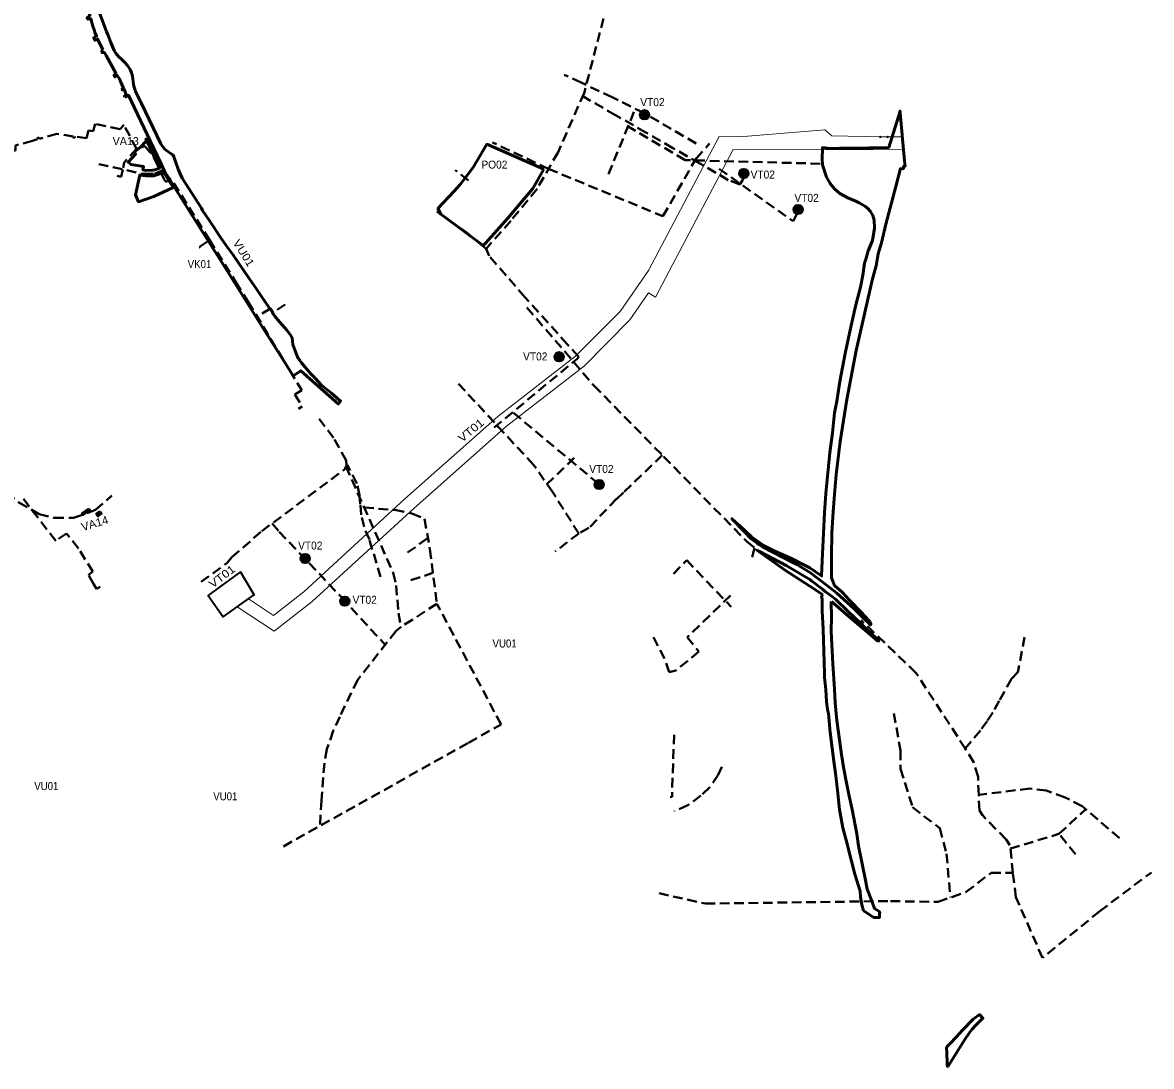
# Model space of a CAD drawing. Extents: x -650145 to -642675, y -1074338 to -1066803.
# Drawn here: x -647369 to -644548, y -1073665 to -1071056 of the extents above; entities that cross this region are included whole.
import ezdxf

# ---------------------------------------------------------------- set-up
doc = ezdxf.new("R2010")
doc.units = 0
doc.header["$LTSCALE"] = 8
doc.header["$PDMODE"] = 32
doc.header["$PDSIZE"] = 4
doc.linetypes.add('MEDIUM_DASHED', pattern=[4.5, 3, -1.5])
for name, color, linetype, lineweight in [('12', 7, 'MEDIUM_DASHED', 40), ('15', 7, 'Continuous', 13), ('45', 7, 'Continuous', 53), ('46', 7, 'Continuous', 53), ('53', 7, 'Continuous', 53), ('60', 7, 'Continuous', 53)]:
    doc.layers.add(name, color=color, linetype=linetype, lineweight=lineweight)
for name, color, linetype in [('17', 7, 'Continuous'), ('2', 7, 'Continuous'), ('3', 7, 'Continuous'), ('5', 7, 'Continuous'), ('8', 7, 'Continuous')]:
    doc.layers.add(name, color=color, linetype=linetype)

msp = doc.modelspace()

# ---------------------------------------------------------------- hatches: boundary and pattern name
at = {"layer": '15'}
for points in [[(-645802.757, -1071286.29, 1), (-645826.282, -1071286.29, 1)], [(-645554.856, -1071433.585, 1), (-645578.381, -1071433.585, 1)], [(-645418.959, -1071522.908, 1), (-645442.484, -1071522.908, 1)], [(-646016.453, -1071890.987, 1), (-646039.978, -1071890.987, 1)], [(-645916.109, -1072210.132, 1), (-645939.634, -1072210.132, 1)], [(-646651.182, -1072395.364, 1), (-646674.706, -1072395.364, 1)], [(-646551.973, -1072501.882, 1), (-646575.498, -1072501.882, 1)]]:
    msp.add_hatch(color=256, dxfattribs=at).paths.add_polyline_path(points)
at = {"layer": '60'}
for points in [[(-647203.48, -1072271.1), (-647219.86, -1072283.16), (-647217.95, -1072285.83), (-647201.52, -1072273.8)], [(-647175.95, -1072277.72), (-647183.77, -1072283.6), (-647179.89, -1072288.9), (-647172.06, -1072283.01)]]:
    msp.add_hatch(color=256, dxfattribs=at).paths.add_polyline_path(points)

# ---------------------------------------------------------------- linework, layer by layer
at = {"layer": '12'}
for p, q in [((-645904.71, -1071434.718), (-645838.309, -1071272.923)), ((-645713.277, -1071399.789), (-645855.82, -1071315.589)), ((-646054.42, -1071421.627), (-646194.458, -1071355.655)), ((-645375.745, -1071408.757), (-645713.277, -1071399.789)), ((-646254.398, -1071450.366), (-646287.777, -1071424.84)), ((-646142.308, -1072031.286), (-645934.368, -1072204.655)), ((-645990.194, -1072143.593), (-646067.454, -1072218.303)), ((-646406.679, -1072380.519), (-646355.921, -1072344.291)), ((-646398.36, -1072449.736), (-646343.369, -1072431.172)), ((-644737.523, -1073134.312), (-644778.948, -1073083.582)), ((-644677.063, -1073276.773), (-644547.878, -1073179.588))]:
    msp.add_line(p, q, dxfattribs=at)
for points in [[(-645889.511, -1070941.335), (-645965.547, -1071232.088), (-646030.617, -1071380.071), (-646083.181, -1071471.838), (-646148.926, -1071551.731), (-646210.712, -1071621.148), (-646257.454, -1071581.884), (-646334.001, -1071528.434)], [(-645685.92, -1071358.056), (-645816.424, -1071281.963), (-645895.068, -1071242.641), (-645972.753, -1071206.196), (-646015.628, -1071186.357)], [(-645568.545, -1071446.977), (-645568.85, -1071448.81), (-645576.682, -1071460.349), (-645605.23, -1071449.68), (-645676.24, -1071408.26), (-645743.83, -1071369.64), (-645811.23, -1071330.74), (-645886.93, -1071287.36), (-645969.116, -1071240.205)], [(-647125.34, -1071322.14), (-647187.77, -1071309.47), (-647192.05, -1071327.84), (-647204.02, -1071325.39), (-647208.89, -1071345.24), (-647238.16, -1071341.03), (-647238.54, -1071343.71), (-647242.66, -1071343.12), (-647242.27, -1071340.44), (-647283.52, -1071334.51), (-647326.47, -1071346.51), (-647327.32, -1071343.47), (-647332.03, -1071344.79), (-647331.18, -1071347.82), (-647344.33, -1071351.49)], [(-647084.37, -1071371.2), (-647115.91, -1071311.35), (-647125.34, -1071322.14)], [(-647344.33, -1071351.49), (-647386.85, -1071363.37), (-647386.8, -1071375.58), (-647438.34, -1071382.93)], [(-647084.37, -1071371.2), (-647115.19, -1071405.75), (-647117.79, -1071418.96)], [(-646901.7, -1071599.29), (-646997.62, -1071446.82), (-647011, -1071454.09), (-647015.17, -1071448), (-647045.84, -1071382.28), (-647050.73, -1071380.13), (-647063.41, -1071364.59), (-647084.37, -1071371.2)], [(-646054.42, -1071421.627), (-645768.62, -1071540.17), (-645685.873, -1071396.078), (-645651.868, -1071358.68)], [(-647178.442, -1071409.986), (-647065.935, -1071434.456), (-647038.805, -1071433.925), (-647016.651, -1071423.819)], [(-647118.63, -1071423.24), (-647122.21, -1071441.39), (-647132.07, -1071439.37)], [(-645627.85, -1071421.652), (-645443.026, -1071552.428), (-645433.722, -1071535.133)], [(-646925.38, -1071619.26), (-646926.8, -1071616.72), (-646901.7, -1071599.29)], [(-646901.7, -1071599.29), (-646836.01, -1071704.74), (-646804.94, -1071754.31)], [(-645979.173, -1071891.235), (-646007.318, -1071860.17), (-646113.522, -1071742.176), (-646203.196, -1071638.82), (-646210.712, -1071621.148)], [(-646804.94, -1071754.31), (-646701.24, -1071925.46), (-646671.37, -1071974.86)], [(-646712.71, -1071760.64), (-646743.06, -1071780.15), (-646749.35, -1071770.55), (-646782.673, -1071791.06)], [(-646108.34, -1071768.288), (-645991.774, -1071903.675), (-645940.8, -1071963.54), (-645766.873, -1072140.424), (-645559.153, -1072352.891), (-645539.728, -1072368.513), (-645547.013, -1072398.199)], [(-646190.163, -1072068.09), (-645983.794, -1071896.963), (-645979.173, -1071891.234)], [(-645978.908, -1072332.844), (-646044.53, -1072228.907), (-646091.859, -1072161.141), (-646284.4, -1071953.541)], [(-646671.37, -1071974.86), (-646688.66, -1071985.16), (-646669.77, -1072015.67), (-646679.35, -1072021.71)], [(-647565.274, -1072012.581), (-647407.42, -1072230.889), (-647378.312, -1072255.368), (-647327.486, -1072284.458), (-647289.597, -1072293.583), (-647241.628, -1072293.997), (-647186.201, -1072273.818), (-647145.51, -1072238.04)], [(-646922.495, -1072453.643), (-646857.191, -1072406.111), (-646845.696, -1072392.061), (-646770.684, -1072326.695), (-646564.651, -1072173.134), (-646559.323, -1072162.51), (-646560.242, -1072150.62), (-646591.477, -1072093.57), (-646627.948, -1072046.396)], [(-646515.621, -1072316.407), (-646522.296, -1072286.272), (-646525.05, -1072259.936), (-646526.73, -1072237.276), (-646533.563, -1072207.871), (-646557.282, -1072161.242)], [(-645770.117, -1072137.125), (-645867.081, -1072230.375), (-645887.539, -1072249.441)], [(-646560.829, -1072165.418), (-646442.617, -1072430.974), (-646435.336, -1072462.744), (-646429.379, -1072531.58), (-646422.811, -1072565.755), (-646435.637, -1072576.085), (-646531.76, -1072698.93), (-646576.398, -1072790.696), (-646592.362, -1072826.343), (-646608.607, -1072871.571), (-646614.559, -1072906.613), (-646622.02, -1072999.792), (-646625.456, -1073063.469)], [(-647191.37, -1072458.86), (-647204.41, -1072436.35), (-647193.17, -1072428.14), (-647228.9, -1072369.98), (-647259.29, -1072332.91), (-647286.03, -1072350.98), (-647368.027, -1072244.683)], [(-645884.618, -1072246.363), (-645953.602, -1072319.058), (-645978.908, -1072332.844), (-646038.138, -1072377.943)], [(-646515.068, -1072268.004), (-646438.375, -1072274.017), (-646395.81, -1072282.852), (-646364.347, -1072296.336), (-646351.055, -1072371.983), (-646333.32, -1072508.549)], [(-646744.92, -1072307.492), (-646727.261, -1072328.683), (-646572.036, -1072491.987), (-646462.937, -1072610.974)], [(-646474.01, -1072441.461), (-646502.208, -1072348.07), (-646515.621, -1072316.407)], [(-645742.473, -1072433.786), (-645709.258, -1072399.404), (-645598.422, -1072516.199)], [(-647175.32, -1072466), (-647184.36, -1072470.98), (-647191.37, -1072458.86)], [(-645599.642, -1072487.459), (-645707.673, -1072591.746), (-645678.856, -1072628.004), (-645736.077, -1072674.835), (-645752.766, -1072679.471), (-645764.412, -1072645.375), (-645793.32, -1072590.47)], [(-646716.85, -1073114.625), (-646254.197, -1072855.664), (-646173.155, -1072809.893), (-646333.32, -1072508.549), (-646422.811, -1072565.755)], [(-644677.063, -1073276.773), (-644820.09, -1073393.239), (-644886.431, -1073241.755), (-644894.218, -1073180.725), (-644901.367, -1073111.484), (-644910.953, -1073097.104), (-644970.414, -1073037.091), (-644977.617, -1073024.956), (-644979.519, -1072985.65), (-644981.225, -1072940.656), (-644991.691, -1072905.052), (-645013.264, -1072869.98), (-645136.284, -1072680.783), (-645273.573, -1072549.71)], [(-644865.163, -1072591.801), (-644881.47, -1072679.739), (-644897.776, -1072696.046), (-644928.014, -1072751.285)], [(-644928.014, -1072751.285), (-644944.228, -1072780.29), (-644958.247, -1072801.452), (-644975.175, -1072824.929), (-645013.264, -1072869.98)], [(-645191.679, -1072782.461), (-645175.001, -1072875.23), (-645175.001, -1072921.093), (-645144.773, -1073016.989), (-645077.02, -1073069.106), (-645059.861, -1073133.007), (-645050.18, -1073242.481)], [(-645740.627, -1072835.69), (-645745.906, -1072985.427), (-645745.265, -1072991.028), (-645750.784, -1072992.05)], [(-645621.405, -1072915.798), (-645630.523, -1072936.275), (-645652.44, -1072967.63), (-645673.716, -1072987.946), (-645706.351, -1073011.942), (-645739.675, -1073026.324)], [(-644627.418, -1073093.922), (-644720.94, -1073014.135), (-644763.53, -1072992.287), (-644810.544, -1072975.14), (-644851.751, -1072970.162), (-644979.519, -1072985.65)], [(-644900.454, -1073120.324), (-644778.948, -1073083.582), (-644712.07, -1073021.703)], [(-645777.988, -1073231.981), (-645662.45, -1073257.758), (-645199.545, -1073251.421), (-645080.605, -1073253.501), (-645010.848, -1073228.236), (-644948.284, -1073180.725), (-644894.218, -1073180.725)]]:
    msp.add_lwpolyline(points, dxfattribs=at)
at = {"layer": '15'}
msp.add_line((-645225.385, -1071341.796), (-645207.234, -1071341.824), dxfattribs=at)
at = {"layer": '15', "lineweight": 35}
msp.add_line((-646832.318, -1072516.145), (-646804.328, -1072496.262), dxfattribs=at)
at = {"layer": '15'}
for points in [[(-645987.337, -1071889.954), (-645875.751, -1071778.476), (-645805.025, -1071675.361), (-645627.872, -1071341.184), (-645577.351, -1071341.261), (-645364.122, -1071324.271), (-645346.46, -1071338.849), (-645225.385, -1071341.796)], [(-645207.234, -1071341.824), (-645170.274, -1071341.88), (-645167.04, -1071373.884), (-645592.784, -1071373.238), (-645786.781, -1071742.105), (-645804.579, -1071731.285)], [(-645804.579, -1071731.285), (-645850.985, -1071798.942), (-645964.716, -1071913.914)], [(-646665.903, -1072478.366), (-646413.327, -1072245.835), (-646181.43, -1072040.387), (-645987.337, -1071889.954)], [(-645964.716, -1071913.914), (-646159.64, -1072064.991), (-646390.555, -1072269.569), (-646645.209, -1072502.744)], [(-646645.209, -1072502.744), (-646739.733, -1072577.115), (-646832.318, -1072516.145), (-646804.328, -1072496.262)], [(-646804.328, -1072496.262), (-646741.387, -1072537.711), (-646665.903, -1072478.366)]]:
    msp.add_lwpolyline(points, dxfattribs=at)
at = {"layer": '15', "lineweight": 35}
msp.add_lwpolyline([(-646824.42, -1072428.58), (-646878.91, -1072468.54), (-646905.18, -1072487.8), (-646867.283, -1072540.984), (-646791.569, -1072487.198), (-646790.354, -1072486.136), (-646810.77, -1072451.09)], close=True, dxfattribs=at)
for centre in [(-645814.519, -1071286.29), (-645566.618, -1071433.585), (-645430.721, -1071522.908), (-646028.216, -1071890.987), (-645927.872, -1072210.132), (-646662.944, -1072395.364), (-646563.736, -1072501.882)]:
    msp.add_circle(centre, 11.762, dxfattribs=at)
at = {"layer": '15'}
for p in [(-645225.385, -1071341.796), (-645207.234, -1071341.824)]:
    msp.add_point(p, dxfattribs=at)
at = {"layer": '45'}
msp.add_line((-645267.525, -1073275.443), (-645271.518, -1073261.16), dxfattribs=at)
msp.add_lwpolyline([(-645222.48, -1071606.08), (-645211.27, -1071560.01), (-645186.67, -1071465.55), (-645175.06, -1071420.93), (-645167.58, -1071421.19), (-645167.37, -1071415.2), (-645163.56, -1071415.3), (-645164.76, -1071401.79), (-645175.4, -1071281.93), (-645175.67, -1071279.45), (-645176.14, -1071277.26), (-645204.341, -1071368.19), (-645243.3, -1071369.02), (-645254.27, -1071369.05), (-645327.08, -1071370.05), (-645348.55, -1071370.559), (-645370.24, -1071368.628), (-645370.24, -1071371.074), (-645370.393, -1071396.574), (-645370.24, -1071411.83), (-645359.64, -1071442), (-645351.06, -1071458.3), (-645340.16, -1071471.63), (-645326.29, -1071483.41), (-645306.77, -1071494.16), (-645286.62, -1071502.67), (-645278.52, -1071506.12), (-645262.36, -1071515.72), (-645255.51, -1071521.55), (-645249.88, -1071528.19), (-645244.4, -1071538.48), (-645240.82, -1071549.6), (-645240.26, -1071569.52), (-645244.81, -1071600.61), (-645248.786, -1071610.383), (-645255.662, -1071626.67), (-645261.094, -1071645.025), (-645264.841, -1071657.687), (-645269.077, -1071687.396), (-645274.868, -1071717.176), (-645286.175, -1071761.228), (-645300.076, -1071820.179), (-645313.153, -1071883.081), (-645326.343, -1071952.807), (-645334.118, -1072001.954), (-645339.455, -1072031.565), (-645344.819, -1072081.225), (-645351.358, -1072130.815), (-645361.317, -1072232.824), (-645364.435, -1072280.268), (-645366.951, -1072331.609), (-645370.624, -1072401.447), (-645372.228, -1072438.764), (-645387.894, -1072427.453), (-645401.441, -1072419.033), (-645414.631, -1072411.611), (-645448.831, -1072394.325), (-645488.64, -1072376.782), (-645515.437, -1072363.447), (-645547.593, -1072340.827), (-645577.33, -1072312.704), (-645579.217, -1072312.425), (-645596.405, -1072296.114), (-645564.4, -1072328.61), (-645547.72, -1072346.19), (-645532.07, -1072358.01), (-645531.65, -1072358.29), (-645528.27, -1072360.53), (-645519.57, -1072366.3), (-645438.64, -1072408.1), (-645437.6, -1072408.64), (-645434.19, -1072410.67), (-645399.77, -1072431.12), (-645371.356, -1072453.119), (-645342.284, -1072475.625), (-645333.62, -1072482.33), (-645290.76, -1072520.92), (-645271.74, -1072539.96), (-645249.9, -1072561.25), (-645248.967, -1072559.511), (-645252.768, -1072552.178), (-645265.009, -1072538.358), (-645272.276, -1072530.154), (-645302.303, -1072499.014), (-645320.805, -1072479.495), (-645339.904, -1072462.677), (-645347.551, -1072443.527), (-645347.677, -1072391.355), (-645346.62, -1072330.914), (-645343.458, -1072278.998), (-645339.908, -1072235.158), (-645335.367, -1072185.207), (-645325.498, -1072102.789), (-645309.01, -1071998.147), (-645285.617, -1071875.733), (-645244.798, -1071696.585), (-645235.793, -1071663.703), (-645230.436, -1071634.261), (-645227.905, -1071625.277)], close=True, dxfattribs=at)
for points in [[(-645462.646, -1072425.015), (-645534.301, -1072374.332), (-645533.08, -1072373.71)], [(-645533.08, -1072373.71), (-645527.33, -1072377.73), (-645459.31, -1072413.95), (-645456.52, -1072415.6), (-645400.12, -1072449.03), (-645396.94, -1072451.44), (-645370.226, -1072471.736)], [(-645369.364, -1072485.931), (-645389.731, -1072471.612), (-645462.646, -1072425.015)], [(-645370.226, -1072471.736), (-645362.81, -1072477.37), (-645345.079, -1072490.836)], [(-645364.524, -1072682.575), (-645366.022, -1072654.462), (-645368.173, -1072571.881), (-645370.755, -1072525.734), (-645370.928, -1072496.619), (-645372.72, -1072490.314), (-645369.364, -1072485.931)], [(-645345.079, -1072490.836), (-645336.33, -1072497.48), (-645306.46, -1072527.08), (-645276.93, -1072555.11), (-645263.7, -1072567.8), (-645242, -1072588.6), (-645241.87, -1072588.722), (-645228.96, -1072600.865), (-645230.845, -1072602.888)], [(-645347.292, -1072502.877), (-645348.253, -1072505.583), (-645347.214, -1072540.97), (-645347.795, -1072577.893), (-645344.152, -1072658.857), (-645339.96, -1072721.587), (-645338.023, -1072755.969), (-645333.718, -1072799.987)], [(-645230.845, -1072602.888), (-645263.217, -1072574.314), (-645298.498, -1072545.352), (-645347.292, -1072502.877)], [(-645357.272, -1072772.771), (-645359.76, -1072752.865), (-645361.874, -1072723.527), (-645362.708, -1072714.781), (-645364.786, -1072692.977), (-645364.524, -1072682.575)], [(-645271.518, -1073261.16), (-645272.747, -1073256.762), (-645275.269, -1073240.71), (-645276.125, -1073226.571), (-645288.647, -1073184.518), (-645297.395, -1073151.294), (-645310.558, -1073098.946), (-645319.052, -1073068.6), (-645327.554, -1073022.214), (-645332.517, -1072974.538), (-645337.34, -1072932.073), (-645340.345, -1072908.029), (-645350.822, -1072830.388), (-645354.019, -1072792.454), (-645355.121, -1072782.993), (-645357.272, -1072772.771)], [(-645333.718, -1072799.987), (-645327.091, -1072848.387), (-645322.284, -1072885.085), (-645317.65, -1072916.642)], [(-645317.65, -1072916.642), (-645311.772, -1072947.945), (-645304.24, -1072985.372), (-645295.788, -1073022.556)], [(-645295.788, -1073022.556), (-645284.269, -1073083.286), (-645279.878, -1073113.356), (-645262.388, -1073199.409), (-645257.842, -1073221.36), (-645247.051, -1073248.736), (-645239.9, -1073270.025), (-645226.847, -1073278.345), (-645227.199, -1073283.366), (-645227.744, -1073292.736), (-645241.72, -1073292.2), (-645263.03, -1073278.25), (-645267.525, -1073275.443)], [(-645060.009, -1073616.53), (-645051.513, -1073608.124), (-645035.303, -1073590.199), (-645020.11, -1073573.585), (-644993.044, -1073546.324), (-644977.924, -1073535.072), (-644969.117, -1073544.254), (-644985.66, -1073560.69), (-644996.41, -1073571.97), (-645001.267, -1073578.582), (-645015.55, -1073599.96), (-645043.35, -1073644.04), (-645056.06, -1073664.2)], [(-645056.06, -1073664.2), (-645057.87, -1073664.55), (-645058.01, -1073661.37), (-645058.42, -1073652.18), (-645058.65, -1073647), (-645058.96, -1073640.09), (-645059.35, -1073631.3), (-645060.009, -1073616.53)]]:
    msp.add_lwpolyline(points, dxfattribs=at)
at = {"layer": '46'}
msp.add_lwpolyline([(-646066.165, -1071422.155), (-646153.5, -1071383.85), (-646208.577, -1071360.044), (-646241.68, -1071416.887), (-646258.487, -1071439.265), (-646275.615, -1071460.886), (-646289.976, -1071477.514), (-646330.914, -1071521.11), (-646324, -1071535), (-646217.978, -1071613.552), (-646211.407, -1071606.247), (-646156.471, -1071545.166), (-646094.063, -1071471.007)], close=True, dxfattribs=at)
at = {"layer": '53'}
for points in [[(-647158.755, -1071078.706), (-647175.93, -1071034.15), (-647179.458, -1071025.505), (-647182.273, -1071016.602), (-647184.357, -1071007.501), (-647188.273, -1070991.778), (-647196.024, -1070957.071), (-647198.121, -1070948.772), (-647200.829, -1070940.652), (-647204.133, -1070932.756), (-647208.015, -1070925.127), (-647215.994, -1070911.999), (-647217.751, -1070909.109), (-647220.159, -1070911.092), (-647224.617, -1070903.278)], [(-647206.4, -1071008.143), (-647220.075, -1071019.169), (-647215.715, -1071024.528), (-647204.286, -1071019.233), (-647200.697, -1071038.069), (-647208.059, -1071044.509), (-647205.591, -1071047.733), (-647198.635, -1071046.314), (-647197.667, -1071050.39), (-647193.273, -1071065.367), (-647190.333, -1071074.194), (-647187.306, -1071082.342), (-647183.964, -1071090.241), (-647191.246, -1071093.802), (-647187.936, -1071100.378), (-647180.976, -1071097.304), (-647179.761, -1071100.174), (-647168.392, -1071123.89), (-647168.218, -1071124.182)], [(-647086.339, -1071228.15), (-647087.881, -1071225.089), (-647090.099, -1071217.849), (-647091.701, -1071210.448), (-647092.676, -1071202.939), (-647094.452, -1071190.358), (-647095.862, -1071184.572), (-647097.779, -1071178.933), (-647100.186, -1071173.486), (-647103.065, -1071168.272), (-647107.059, -1071162.516), (-647111.594, -1071157.174), (-647116.626, -1071152.299), (-647123.193, -1071146.218), (-647128.019, -1071141.712), (-647132.407, -1071136.78), (-647136.32, -1071131.464), (-647139.726, -1071125.808), (-647142.594, -1071119.862), (-647148.656, -1071105.574), (-647155.067, -1071088.05), (-647158.755, -1071078.706)], [(-647168.218, -1071124.182), (-647170.805, -1071127.15), (-647169.97, -1071130.957), (-647164.211, -1071130.957), (-647159.971, -1071138.546), (-647134.812, -1071183.839)], [(-647134.812, -1071183.839), (-647140.658, -1071187.529), (-647138.118, -1071191.777), (-647132.152, -1071188.189), (-647130.448, -1071190.898), (-647126.947, -1071197.043), (-647123.419, -1071205.112), (-647116.773, -1071219.678), (-647120.397, -1071222.418), (-647118.924, -1071224.429), (-647115.708, -1071222.03), (-647113.565, -1071226.769), (-647111.09, -1071233.861), (-647110.86, -1071235.542), (-647114.424, -1071239.692), (-647113.406, -1071242.178)], [(-647023.313, -1071359.214), (-647071.319, -1071257.978), (-647086.339, -1071228.15)], [(-647113.406, -1071242.178), (-647104.441, -1071237.888), (-647089.673, -1071267.215), (-647041.473, -1071369.168), (-647032.683, -1071388.188), (-647023.672, -1071407.104)], [(-646993.692, -1071385.443), (-646997.314, -1071384.184), (-647009.131, -1071376.004), (-647013.078, -1071372.395), (-647016.716, -1071368.473), (-647020.163, -1071364.062), (-647023.313, -1071359.214)], [(-646802.675, -1071695.976), (-646843.803, -1071635.879), (-646855.534, -1071619.072), (-646871.486, -1071596.093), (-646902.634, -1071550.043), (-646918.814, -1071525.773), (-646922.091, -1071519.755), (-646969.957, -1071445.257), (-646975.436, -1071434.358), (-646979.727, -1071422.319), (-646985.599, -1071405.901), (-646990.688, -1071391.364), (-646993.692, -1071385.443)], [(-647023.672, -1071407.104), (-647014.83, -1071425.33), (-647011.36, -1071432.03), (-647008.63, -1071436.45), (-646975.61, -1071488.87), (-646942.96, -1071540.79), (-646909.21, -1071594.65), (-646876.14, -1071646.98), (-646839.09, -1071705.6), (-646762.26, -1071827.94), (-646728.98, -1071880.75), (-646705.18, -1071918.5), (-646692.521, -1071938.461)], [(-646692.521, -1071938.461), (-646673.72, -1071926.184), (-646579.995, -1072008.875), (-646574.347, -1072001.788), (-646590.893, -1071987.114), (-646597.11, -1071982.01), (-646621.434, -1071962.285), (-646637.013, -1071945.639), (-646649.491, -1071933.3), (-646672.097, -1071906.51), (-646676.164, -1071900.743), (-646677.095, -1071899.057), (-646680.054, -1071894.36), (-646682.232, -1071889.581), (-646693.376, -1071860.924), (-646695.001, -1071844.225), (-646699.832, -1071835.287), (-646708.716, -1071824.655), (-646720.377, -1071811.708), (-646726.457, -1071804.237), (-646738.49, -1071789.831), (-646741.611, -1071785.306), (-646744.615, -1071780.844), (-646770.308, -1071743.104), (-646785.058, -1071720.869), (-646802.675, -1071695.976)]]:
    msp.add_lwpolyline(points, dxfattribs=at)
at = {"layer": '60'}
for points in [[(-647056.48, -1071355.32), (-647060.6, -1071346.87), (-647060.22, -1071349.87), (-647061.4, -1071352.51), (-647062.78, -1071354.77), (-647073.68, -1071366.75), (-647075.25, -1071368.01), (-647083.48, -1071374.62), (-647090.04, -1071379.44), (-647088.57, -1071381.97), (-647086.45, -1071384.59), (-647105.2, -1071404.54), (-647097.5, -1071410.96), (-647066.35, -1071415.79), (-647068.162, -1071424.298), (-647061.23, -1071425.434), (-647043.137, -1071424.978), (-647038.119, -1071424.37), (-647026.472, -1071419.614), (-647035.47, -1071400.31)], [(-647015.484, -1071430.864), (-647040.878, -1071438.769), (-647060.532, -1071439.002), (-647076.037, -1071437.073), (-647086.716, -1071486.782), (-647079.168, -1071503.954), (-647040.889, -1071490.395), (-646992.555, -1071467.975)], [(-647203.48, -1072271.1), (-647219.86, -1072283.16), (-647217.95, -1072285.83), (-647201.52, -1072273.8)], [(-647175.95, -1072277.72), (-647183.77, -1072283.6), (-647179.89, -1072288.9), (-647172.06, -1072283.01)]]:
    msp.add_lwpolyline(points, close=True, dxfattribs=at)

# ---------------------------------------------------------------- texts
at = {"layer": '17', "width": 0.95}
for p in [(-645825.148, -1071264.946), (-645549.442, -1071445.886), (-645439.959, -1071504.162), (-646118.047, -1071900.373), (-645952.7, -1072181.661), (-646680.229, -1072372.978), (-646544.334, -1072508.451)]:
    msp.add_text('VT02', height=20, dxfattribs=at).set_placement(p)
at = {"layer": '17', "width": 1.15}
for rotation, p in [(39.483, (-646270.392, -1072106.216)), (37.163, (-646893.836, -1072470.401))]:
    msp.add_text('VT01', height=20, rotation=rotation, dxfattribs=at).set_placement(p)
at = {"layer": '2', "width": 1.1}
msp.add_text('VU01', height=20, rotation=302.088, dxfattribs=at).set_placement((-646844.301, -1071605.934))
at = {"layer": '2', "width": 0.9}
for p in [(-646194.406, -1072617.656), (-647339.543, -1072974.017), (-646892.266, -1072999.605)]:
    msp.add_text('VU01', height=20, dxfattribs=at).set_placement(p)
at = {"layer": '3'}
msp.add_text('VA13', height=20, dxfattribs=at).set_placement((-647143.769, -1071362.286))
at = {"layer": '3', "width": 1.05}
msp.add_text('VA14', height=20, rotation=16.632, dxfattribs=at).set_placement((-647218.51, -1072326.887))
at = {"layer": '5', "width": 0.95}
msp.add_text('PO02', height=20, dxfattribs=at).set_placement((-646222.248, -1071421.051))
at = {"layer": '8', "width": 0.9}
msp.add_text('VK01', height=20, dxfattribs=at).set_placement((-646956.144, -1071669.572))

doc.saveas('drawing.dxf')
